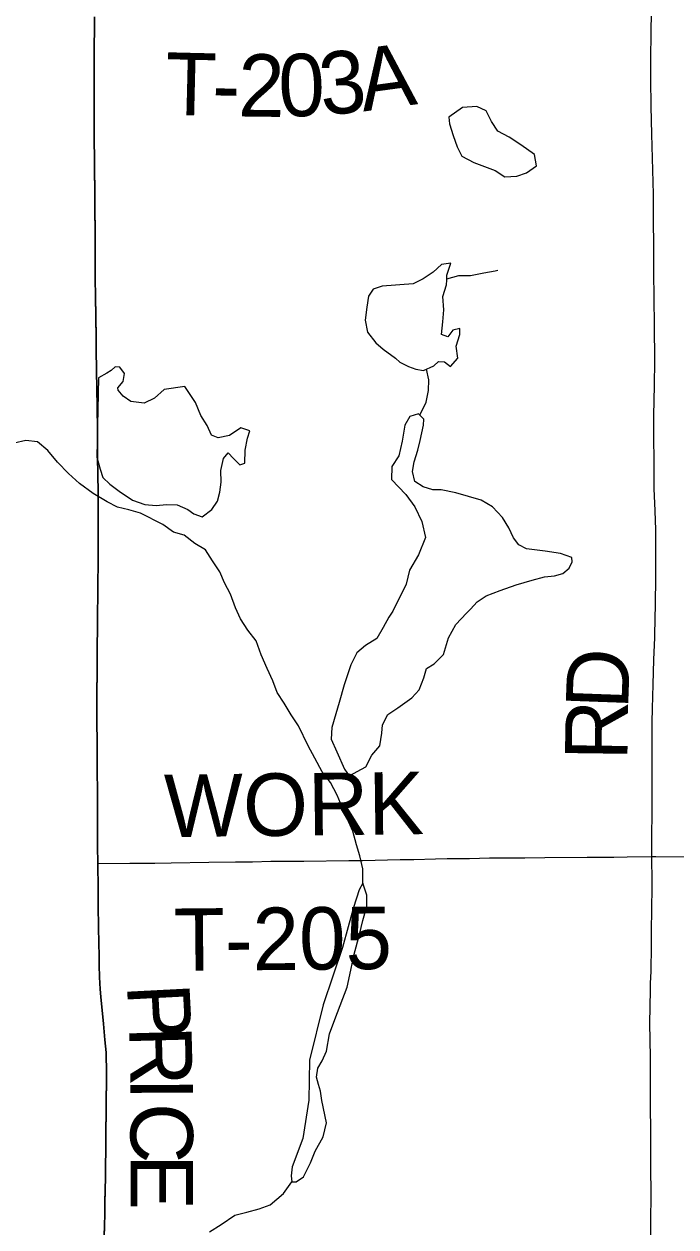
# Model space of a CAD drawing. Extents: x 0 to 34, y 0 to 22.
# Drawn here: x 4.956 to 5.549, y 18.712 to 19.806 of the extents above; entities that cross this region are included whole.
import ezdxf

# ---------------------------------------------------------------- set-up
doc = ezdxf.new("R2010")
doc.units = 0
for name, color, linetype in [('GM_X_Corporation', 7, 'Continuous'), ('GM_X_County_Road', 7, 'Continuous'), ('GM_X_County_Road_Text', 7, 'Continuous'), ('GM_X_Minor_Lake', 7, 'Continuous'), ('GM_X_Minor_River', 7, 'Continuous'), ('GM_X_Township_Road', 7, 'Continuous'), ('GM_X_Township_Road_Text', 7, 'Continuous')]:
    doc.layers.add(name, color=color, linetype=linetype)

msp = doc.modelspace()

# ---------------------------------------------------------------- linework, layer by layer
at = {"layer": 'GM_X_Corporation'}
for points in [[(5.0292, 18.7031), (5.0294, 18.7134), (5.0297, 18.7229), (5.0299, 18.7342), (5.0301, 18.7455), (5.0303, 18.7567), (5.0304, 18.767), (5.0306, 18.7819), (5.0307, 18.796), (5.0311, 18.819), (5.0312, 18.8289), (5.0314, 18.8426), (5.0315, 18.8495), (5.0315, 18.8571), (5.0312, 18.8647), (5.0309, 18.8703), (5.0299, 18.8819), (5.0286, 18.8964), (5.0262, 18.9209), (5.0257, 18.928), (5.0254, 18.9333), (5.0251, 18.9389), (5.0248, 18.9498), (5.0246, 18.9583), (5.0243, 18.9698), (5.0241, 18.9843), (5.0238, 19.0038), (5.0237, 19.0187), (5.0236, 19.0429), (5.0233, 19.0574), (5.0232, 19.0735), (5.0232, 19.0974), (5.0231, 19.1086), (5.023, 19.1259), (5.0229, 19.1397), (5.0229, 19.1491), (5.0227, 19.1749), (5.0227, 19.1943), (5.0229, 19.2204), (5.023, 19.2435), (5.0231, 19.2528), (5.0232, 19.2703), (5.0234, 19.2856), (5.0234, 19.2954), (5.0237, 19.317), (5.0239, 19.3389), (5.0239, 19.3524), (5.0237, 19.3762), (5.0234, 19.4002), (5.0233, 19.4082), (5.0232, 19.4277), (5.0232, 19.4418), (5.023, 19.4531), (5.0229, 19.4605), (5.0227, 19.4715), (5.0222, 19.4937), (5.022, 19.5074), (5.0218, 19.5197), (5.0215, 19.5412), (5.0212, 19.5574), (5.021, 19.5755), (5.0209, 19.5989), (5.0209, 19.6097), (5.0203, 19.6824), (5.0202, 19.7019), (5.0202, 19.7206), (5.0201, 19.7659), (5.0202, 19.7838), (5.0203, 19.8037), (5.0204, 19.8126)], [(5.0292, 18.7031), (5.0294, 18.7134), (5.0297, 18.7229), (5.0299, 18.7342), (5.0301, 18.7455), (5.0303, 18.7567), (5.0304, 18.767), (5.0306, 18.7819), (5.0307, 18.796), (5.0311, 18.819), (5.0312, 18.8289), (5.0314, 18.8426), (5.0315, 18.8495), (5.0315, 18.8571), (5.0312, 18.8647), (5.0309, 18.8703), (5.0299, 18.8819), (5.0286, 18.8964), (5.0262, 18.9209), (5.0257, 18.928), (5.0254, 18.9333), (5.0251, 18.9389), (5.0248, 18.9498), (5.0246, 18.9583), (5.0243, 18.9698), (5.0241, 18.9843), (5.0238, 19.0038), (5.0237, 19.0187), (5.0236, 19.0429), (5.0233, 19.0574), (5.0232, 19.0735), (5.0232, 19.0974), (5.0231, 19.1086), (5.023, 19.1259), (5.0229, 19.1397), (5.0229, 19.1491), (5.0227, 19.1749), (5.0227, 19.1943), (5.0229, 19.2204), (5.023, 19.2435), (5.0231, 19.2528), (5.0232, 19.2703), (5.0234, 19.2856), (5.0234, 19.2954), (5.0237, 19.317), (5.0239, 19.3389), (5.0239, 19.3524), (5.0237, 19.3762), (5.0234, 19.4002), (5.0233, 19.4082), (5.0232, 19.4277), (5.0232, 19.4418), (5.023, 19.4531), (5.0229, 19.4605), (5.0227, 19.4715), (5.0222, 19.4937), (5.022, 19.5074), (5.0218, 19.5197), (5.0215, 19.5412), (5.0212, 19.5574), (5.021, 19.5755), (5.0209, 19.5989), (5.0209, 19.6097), (5.0203, 19.6824), (5.0202, 19.7019), (5.0202, 19.7206), (5.0201, 19.7659), (5.0202, 19.7838), (5.0203, 19.8037), (5.0204, 19.8126)], [(5.0204, 19.8126), (5.0203, 19.8037), (5.0202, 19.7838), (5.0201, 19.7659), (5.0202, 19.7206), (5.0202, 19.7019), (5.0203, 19.6824), (5.0209, 19.6097), (5.0209, 19.5989), (5.021, 19.5755), (5.0212, 19.5574), (5.0215, 19.5412), (5.0218, 19.5197), (5.022, 19.5074), (5.0222, 19.4937), (5.0227, 19.4715), (5.0229, 19.4605), (5.023, 19.4531), (5.0232, 19.4418), (5.0232, 19.4277), (5.0233, 19.4082), (5.0234, 19.4002), (5.0237, 19.3762), (5.0239, 19.3524), (5.0239, 19.3389), (5.0237, 19.317), (5.0234, 19.2954), (5.0234, 19.2856), (5.0232, 19.2703), (5.0231, 19.2528), (5.023, 19.2435), (5.0229, 19.2204), (5.0227, 19.1943), (5.0227, 19.1749), (5.0229, 19.1491), (5.0229, 19.1397), (5.023, 19.1259), (5.0231, 19.1086), (5.0232, 19.0974), (5.0232, 19.0735), (5.0233, 19.0574), (5.0236, 19.0429), (5.0237, 19.0187), (5.0238, 19.0038), (5.0241, 18.9843), (5.0243, 18.9698), (5.0246, 18.9583), (5.0248, 18.9498), (5.0251, 18.9389), (5.0254, 18.9333), (5.0257, 18.928), (5.0262, 18.9209), (5.0286, 18.8964), (5.0299, 18.8819), (5.0309, 18.8703), (5.0312, 18.8647), (5.0315, 18.8571), (5.0315, 18.8495), (5.0314, 18.8426), (5.0312, 18.8289), (5.0311, 18.819), (5.0307, 18.796), (5.0306, 18.7819), (5.0304, 18.767), (5.0303, 18.7567), (5.0301, 18.7455), (5.0299, 18.7342), (5.0297, 18.7229), (5.0294, 18.7134), (5.0292, 18.7031)]]:
    msp.add_lwpolyline(points, dxfattribs=at)
at = {"layer": 'GM_X_County_Road'}
for points in [[(5.5276, 19.0487), (5.5275, 19.0524), (5.5275, 19.0623), (5.5277, 19.0934), (5.5279, 19.1362), (5.5278, 19.1604), (5.5279, 19.1709), (5.5282, 19.1833), (5.5287, 19.2053), (5.5294, 19.2275), (5.5301, 19.2479), (5.5303, 19.2529), (5.5304, 19.2621), (5.531, 19.2994), (5.531, 19.3193), (5.531, 19.3459), (5.5304, 19.3631), (5.5296, 19.3836), (5.5295, 19.4091), (5.5293, 19.4296), (5.5294, 19.4501), (5.53, 19.4774), (5.5302, 19.4998), (5.5299, 19.5321), (5.5293, 19.5806), (5.5289, 19.6514), (5.5276, 19.7061), (5.5269, 19.731), (5.5267, 19.7559), (5.5267, 19.7751), (5.5268, 19.7974), (5.5271, 19.8178)], [(5.5266, 18.6847), (5.5265, 18.7126), (5.527, 18.7455), (5.5267, 18.7622), (5.5267, 18.7828), (5.5267, 18.8008), (5.5264, 18.8194), (5.5263, 18.8399), (5.5262, 18.866), (5.526, 18.8815), (5.5258, 18.8971), (5.5262, 18.927), (5.5264, 18.9331), (5.5268, 18.9443), (5.5271, 18.9673), (5.5272, 18.9809), (5.5278, 19.0207), (5.5278, 19.0263), (5.5276, 19.0474), (5.5276, 19.0487)]]:
    msp.add_lwpolyline(points, dxfattribs=at)
at = {"layer": 'GM_X_Minor_Lake'}
for p, q in [((5.3656, 19.6802), (5.3849, 19.6728)), ((5.3104, 19.5698), (5.282, 19.5677)), ((5.0242, 19.4841), (5.0225, 19.412)), ((5.3041, 19.2964), (5.2919, 19.2719)), ((5.2462, 18.9658), (5.2284, 18.9137))]:
    msp.add_line(p, q, dxfattribs=at)
for points in [[(5.3849, 19.6728), (5.3937, 19.6671), (5.4046, 19.6676), (5.4133, 19.6707), (5.4224, 19.6772), (5.4208, 19.6874), (5.4082, 19.6961), (5.3976, 19.7032), (5.3873, 19.7088), (5.3816, 19.7175), (5.3769, 19.7273), (5.3682, 19.731), (5.3553, 19.7302), (5.3429, 19.7214), (5.3433, 19.7153), (5.3468, 19.7047), (5.3503, 19.6945), (5.3545, 19.6858), (5.3656, 19.6802)], [(5.282, 19.5677), (5.2741, 19.5649), (5.2696, 19.5585), (5.2682, 19.5486), (5.2668, 19.5368), (5.2687, 19.5258), (5.2764, 19.516), (5.2832, 19.5104), (5.2943, 19.5021), (5.2981, 19.4984), (5.3061, 19.4946), (5.3129, 19.492), (5.3197, 19.491), (5.3291, 19.4952), (5.3333, 19.499), (5.339, 19.4987), (5.3443, 19.4946), (5.351, 19.5022), (5.3494, 19.5132), (5.3528, 19.5238), (5.3527, 19.5291), (5.3463, 19.5276), (5.3418, 19.5215), (5.3361, 19.5237), (5.3372, 19.5351), (5.3382, 19.5461), (5.3374, 19.5582), (5.3407, 19.5689), (5.341, 19.573), (5.341, 19.5776), (5.3447, 19.5886), (5.336, 19.5874), (5.3285, 19.5805), (5.3194, 19.5744), (5.3104, 19.5698)], [(5.0225, 19.412), (5.0256, 19.4011), (5.0279, 19.3935), (5.0344, 19.3875), (5.0428, 19.3811), (5.0549, 19.3728), (5.0663, 19.3691), (5.0766, 19.3681), (5.086, 19.3689), (5.0955, 19.3686), (5.1053, 19.3645), (5.1107, 19.3604), (5.1183, 19.3578), (5.1273, 19.3643), (5.1322, 19.3719), (5.1344, 19.3803), (5.1358, 19.3894), (5.1353, 19.4), (5.1379, 19.4107), (5.142, 19.416), (5.147, 19.4107), (5.1527, 19.4051), (5.1572, 19.4066), (5.1575, 19.4184), (5.1597, 19.4294), (5.1616, 19.4359), (5.1536, 19.4388), (5.1434, 19.4319), (5.1328, 19.4296), (5.1268, 19.4322), (5.1229, 19.4409), (5.1172, 19.4499), (5.1122, 19.4617), (5.1026, 19.4764), (5.0837, 19.4736), (5.075, 19.4656), (5.0656, 19.4613), (5.0535, 19.4627), (5.0466, 19.4676), (5.0421, 19.4729), (5.0417, 19.4752), (5.0465, 19.4809), (5.0476, 19.4881), (5.0434, 19.4938), (5.0392, 19.4941), (5.0355, 19.491), (5.0317, 19.4884), (5.0242, 19.4841)], [(5.2919, 19.2719), (5.2881, 19.2665), (5.2829, 19.257), (5.2773, 19.2471), (5.2671, 19.2406), (5.2592, 19.2341), (5.2537, 19.223), (5.2477, 19.2048), (5.2429, 19.1888), (5.24, 19.1785), (5.2363, 19.166), (5.2356, 19.1554), (5.241, 19.144), (5.248, 19.1282), (5.2522, 19.1221), (5.2672, 19.1302), (5.2728, 19.1409), (5.28, 19.1493), (5.2818, 19.161), (5.2825, 19.1686), (5.2873, 19.1778), (5.2963, 19.1839), (5.3091, 19.1931), (5.3159, 19.2004), (5.32, 19.2114), (5.3226, 19.2198), (5.3293, 19.224), (5.338, 19.2324), (5.3424, 19.2476), (5.3491, 19.2598), (5.3589, 19.2701), (5.3626, 19.2739), (5.3686, 19.2804), (5.3769, 19.2858), (5.3894, 19.2908), (5.4041, 19.2959), (5.4185, 19.3002), (5.4298, 19.3033), (5.4389, 19.3041), (5.4464, 19.3061), (5.4524, 19.311), (5.455, 19.3168), (5.4546, 19.3209), (5.4444, 19.3243), (5.4304, 19.3264), (5.4133, 19.3286), (5.4065, 19.3323), (5.4015, 19.3387), (5.3973, 19.3478), (5.3915, 19.3572), (5.3824, 19.367), (5.3721, 19.373), (5.3493, 19.3797), (5.3357, 19.3822), (5.3281, 19.3822), (5.3194, 19.3851), (5.3118, 19.39), (5.3098, 19.3991), (5.3113, 19.4078), (5.3146, 19.4185), (5.3168, 19.4272), (5.3197, 19.4413), (5.3201, 19.4466), (5.3151, 19.4515), (5.3072, 19.4491), (5.3027, 19.4411), (5.3002, 19.4267), (5.2972, 19.4134), (5.2909, 19.4035), (5.2906, 19.3917), (5.3036, 19.3782), (5.312, 19.3669), (5.3181, 19.3536), (5.3216, 19.3389), (5.3153, 19.3233), (5.3071, 19.3092), (5.3041, 19.2964)], [(5.2284, 18.9137), (5.2159, 18.8635), (5.2155, 18.8271), (5.2101, 18.7922), (5.2004, 18.7663), (5.1993, 18.758), (5.2001, 18.7527), (5.2039, 18.7527), (5.2107, 18.7573), (5.217, 18.7699), (5.2211, 18.7805), (5.2286, 18.7935), (5.2315, 18.8064), (5.2272, 18.8268), (5.226, 18.8352), (5.2241, 18.8412), (5.2225, 18.848), (5.2236, 18.856), (5.2277, 18.8629), (5.2314, 18.8716), (5.2343, 18.8872), (5.2391, 18.9005), (5.2439, 18.9131), (5.2502, 18.9298), (5.2535, 18.9454), (5.2568, 18.9598), (5.2616, 18.9777), (5.2645, 18.9906), (5.2682, 19.0032), (5.2681, 19.0134), (5.2647, 19.0244), (5.2613, 19.0183), (5.2561, 19.0023), (5.2513, 18.9848), (5.2462, 18.9658)]]:
    msp.add_lwpolyline(points, dxfattribs=at)
at = {"layer": 'GM_X_Minor_River'}
for points in [[(5.341, 19.5743), (5.352, 19.5773), (5.3626, 19.5774), (5.3747, 19.5798), (5.3849, 19.5817), (5.3875, 19.5821)], [(5.3164, 19.4502), (5.3222, 19.4621), (5.3244, 19.4728), (5.3247, 19.4823), (5.3225, 19.4922)], [(5.2647, 19.0244), (5.2646, 19.0376), (5.2618, 19.0494), (5.2587, 19.0592), (5.2556, 19.0717), (5.2502, 19.0834), (5.2456, 19.0936), (5.2413, 19.1046), (5.2352, 19.1159), (5.2275, 19.1257), (5.221, 19.1382), (5.2149, 19.1495), (5.206, 19.1677), (5.1995, 19.1775), (5.193, 19.1881), (5.1865, 19.1979), (5.1826, 19.2085), (5.1776, 19.2198), (5.1722, 19.2323), (5.1676, 19.2448), (5.1599, 19.2546), (5.1534, 19.2651), (5.1488, 19.2749), (5.1442, 19.2874), (5.1388, 19.2976), (5.1345, 19.3078), (5.1277, 19.3176), (5.1215, 19.3278), (5.1116, 19.3335), (5.1021, 19.341), (5.0923, 19.3439), (5.0827, 19.3507), (5.0622, 19.3611), (5.0516, 19.3641), (5.0414, 19.3667), (5.0319, 19.3715), (5.0193, 19.379), (5.0068, 19.388), (4.9968, 19.3971), (4.9869, 19.4076), (4.9781, 19.4181), (4.9686, 19.426), (4.958, 19.4271), (4.9474, 19.4247)], [(5.1252, 18.7073), (5.1357, 18.7139), (5.1481, 18.7223), (5.1591, 18.725), (5.1701, 18.7282), (5.1802, 18.7317), (5.1923, 18.742), (5.2001, 18.7527)]]:
    msp.add_lwpolyline(points, dxfattribs=at)
at = {"layer": 'GM_X_Township_Road'}
for points in [[(5.0238, 19.0423), (5.0235, 19.0568), (5.0234, 19.0729), (5.0234, 19.0968), (5.0233, 19.1081), (5.0232, 19.1253), (5.0231, 19.1391), (5.0231, 19.1486), (5.0229, 19.1743), (5.0229, 19.1938), (5.0231, 19.2199), (5.0233, 19.2429), (5.0233, 19.2523), (5.0235, 19.2697), (5.0236, 19.285), (5.0236, 19.2949), (5.0239, 19.3165), (5.0241, 19.3383), (5.0241, 19.3518), (5.0239, 19.3756), (5.0237, 19.3996), (5.0236, 19.4076), (5.0235, 19.4271), (5.0234, 19.4412), (5.0232, 19.4525), (5.0232, 19.4599), (5.0229, 19.471), (5.0224, 19.4932), (5.0222, 19.5068), (5.022, 19.5192), (5.0217, 19.5406), (5.0214, 19.5569), (5.0212, 19.5749), (5.0211, 19.5984), (5.0211, 19.6091), (5.0205, 19.6818), (5.0204, 19.7014), (5.0204, 19.7201), (5.0203, 19.7654), (5.0204, 19.7832), (5.0205, 19.8031), (5.0206, 19.812)], [(5.0238, 19.0423), (5.0525, 19.0425), (5.0754, 19.0427), (5.0903, 19.0428), (5.1245, 19.0434), (5.1487, 19.0437), (5.1642, 19.0439), (5.181, 19.0445), (5.2108, 19.0446), (5.2518, 19.0451), (5.2642, 19.0452), (5.2984, 19.046), (5.3108, 19.0461), (5.3307, 19.0465), (5.3412, 19.0468), (5.3617, 19.0469), (5.3797, 19.0474), (5.3915, 19.0476), (5.412, 19.0476), (5.43, 19.0477), (5.4685, 19.048), (5.4928, 19.0481), (5.5051, 19.0484), (5.5276, 19.0487)], [(5.5276, 19.0487), (5.5311, 19.0488), (5.5677, 19.0485)], [(5.0294, 18.7025), (5.0297, 18.7128), (5.0299, 18.7224), (5.0301, 18.7337), (5.0303, 18.7449), (5.0305, 18.7561), (5.0306, 18.7664), (5.0308, 18.7814), (5.0309, 18.7954), (5.0313, 18.8185), (5.0314, 18.8283), (5.0316, 18.8421), (5.0317, 18.8489), (5.0317, 18.8565), (5.0314, 18.8642), (5.0311, 18.8697), (5.0301, 18.8813), (5.0288, 18.8959), (5.0264, 18.9203), (5.0259, 18.9275), (5.0256, 18.9328), (5.0253, 18.9384), (5.025, 18.9493), (5.0248, 18.9577), (5.0246, 18.9692), (5.0243, 18.9838), (5.024, 19.0032), (5.0239, 19.0182), (5.0238, 19.0423)]]:
    msp.add_lwpolyline(points, dxfattribs=at)

# ---------------------------------------------------------------- texts
at = {"layer": 'GM_X_County_Road_Text'}
for s, rotation, p in [('D', 87.8976, (5.5058, 19.1822)), ('R', 89.2467, (5.5052, 19.1359))]:
    msp.add_text(s, height=0.0568, rotation=rotation, dxfattribs=at).set_placement(p)
at = {"layer": 'GM_X_Township_Road_Text'}
for s, height, rotation, p in [('T', 0.0568, 358.6156, (5.0844, 19.7237)), ('2', 0.0568, 359.2833, (5.1509, 19.7221)), ('0', 0.0568, 1.6589, (5.1885, 19.7217)), ('3', 0.0568, 5.2974, (5.2274, 19.723)), ('A', 0.0568, 7.7525, (5.2649, 19.7265)), ('-', 0.0568, 358.7517, (5.127, 19.7226)), ('WORK', 0.05682, 0.6735, (5.0841, 19.0663)), ('T-205', 0.05682, 0.5557, (5.0928, 18.9445)), ('P', 0.0568, 272.9663, (5.0499, 18.9319)), ('R', 0.0568, 271.5457, (5.0518, 18.894)), ('I', 0.0568, 270.3279, (5.0531, 18.8477)), ('C', 0.0568, 270.0156, (5.0532, 18.8244)), ('E', 0.0568, 270, (5.0532, 18.7778))]:
    msp.add_text(s, height=height, rotation=rotation, dxfattribs=at).set_placement(p)

doc.saveas('drawing.dxf')
